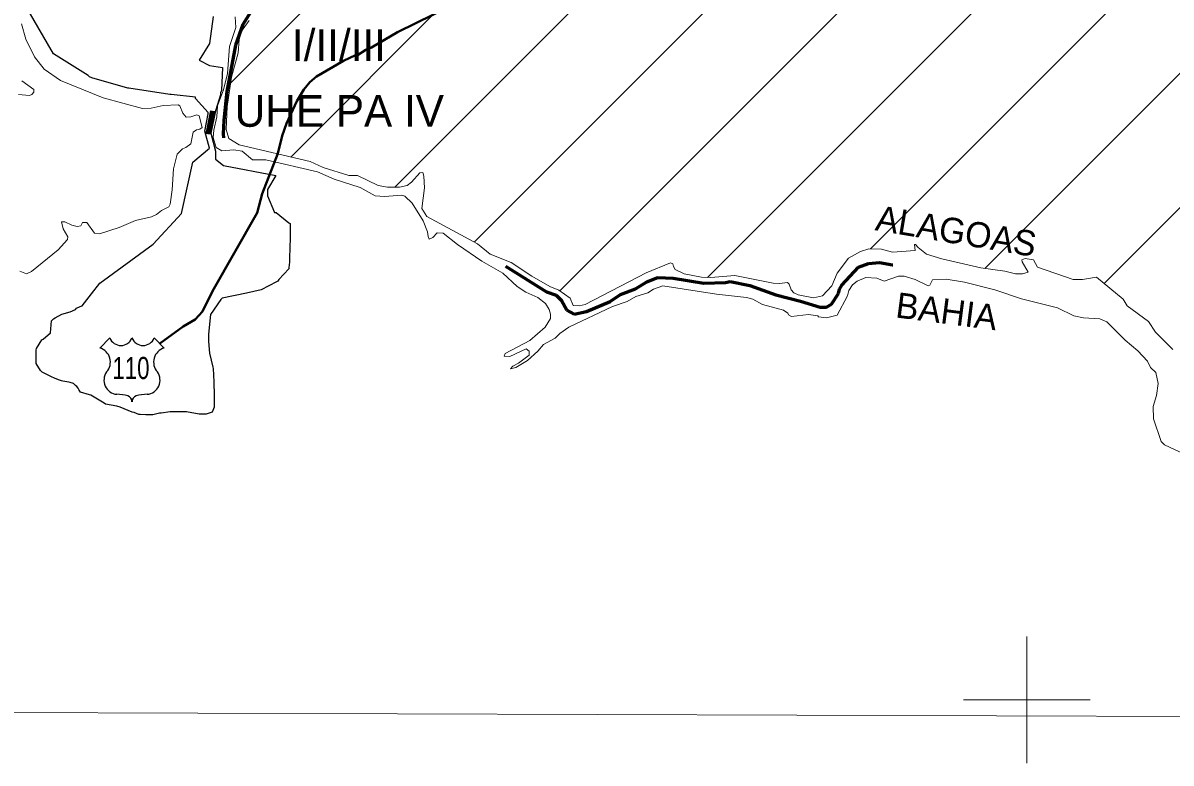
# Model space of a CAD drawing. Extents: x 553962 to 842807, y 8883888 to 9032388.
# Drawn here: x 584142 to 602280, y 8949000 to 8960686 of the extents above; entities that cross this region are included whole.
import ezdxf
from ezdxf.enums import TextEntityAlignment as Align

# ---------------------------------------------------------------- set-up
doc = ezdxf.new("R2010")
doc.units = 0
doc.header["$LTSCALE"] = 160
doc.linetypes.add('LONG_DASH_SHORT_DASH', pattern=[9.9, 6, -1.2, 1.5, -1.2])
for name, color, linetype, lineweight in [('1', 7, 'Continuous', 13), ('11', 7, 'Continuous', 25), ('15', 7, 'Continuous', 25), ('2', 7, 'Continuous', 13), ('21', 7, 'Continuous', 25), ('22', 7, 'Continuous', 35), ('27', 7, 'Continuous', 90), ('28', 7, 'Continuous', 13), ('30', 7, 'Continuous', 13), ('34', 7, 'LONG_DASH_SHORT_DASH', 60)]:
    doc.layers.add(name, color=color, linetype=linetype, lineweight=lineweight)

msp = doc.modelspace()

# ---------------------------------------------------------------- linework, layer by layer
at = {"layer": '1'}
for p, q in [((600000, 8949000), (600000, 8951000)), ((599000, 8950000), (601000, 8950000))]:
    msp.add_line(p, q, dxfattribs=at)
at = {"layer": '11'}
for p, q in [((585355.1, 8955553.3), (585515, 8955713.2)), ((586214.4, 8955713.2), (586374.3, 8955553.3))]:
    msp.add_line(p, q, dxfattribs=at)
for centre, radius, start, end in [((585689.9, 8955780.2), 187.2, 200.95927, 339.04073), ((586039.5, 8955780.2), 187.2, 200.95927, 339.04073), ((585293, 8955331.4), 230.3, 317.5721, 74.36886), ((586436.4, 8955331.4), 230.3, 105.62774, 222.4279), ((585646.5, 8955046.3), 224.7, 144.73733, 264.65778), ((586082.9, 8955046.3), 224.7, 275.34222, 35.26267), ((585624.6, 8954232.8), 589.7, 72.89371, 89.90057), ((585770.3, 8954706.2), 94.4, 357.69345, 72.92955), ((585959.1, 8954706.2), 94.4, 107.07045, 182.30655), ((586104.8, 8954232.8), 589.7, 90.09943, 107.10629)]:
    msp.add_arc(centre, radius, start, end, dxfattribs=at)
at = {"layer": '15', "lineweight": 40}
for points in [[(587134, 8956453.8), (587843.6, 8957685.7), (587923.7, 8957988.5), (588169.9, 8958625.1), (588237, 8958904.7), (588304.1, 8959099.5), (588468, 8959448.9), (588578.9, 8959635.8), (588673.7, 8959750.1), (588777.5, 8959843.1), (589203.6, 8960089.7), (589393.4, 8960175.8), (589428.5, 8960178.5), (589560.1, 8960264.6), (589648.9, 8960297.2), (590059.4, 8960543.5), (591188.1, 8961101.4)], [(586304.3, 8955623.3), (586671.7, 8955893.4), (586864.3, 8956001.7), (586980.3, 8956129.6), (587134, 8956453.8)]]:
    msp.add_lwpolyline(points, dxfattribs=at)
at = {"layer": '2'}
msp.add_line((565315.3, 8949866.8), (791497.7, 8949052.2), dxfattribs=at)
at = {"layer": '21', "lineweight": 13}
for points in [[(587493.3, 8960783.2), (587506.9, 8960616.2), (587403.7, 8960314.5), (587373.8, 8959887.7), (587311.1, 8959628.3), (587213.9, 8959375.4), (587204.9, 8959204), (587155.6, 8958993.5), (587145.5, 8958878.4), (587193.6, 8958719.2), (587281.8, 8958666.6), (587474.7, 8958681.2), (587603.9, 8958663), (587767.8, 8958525.1), (587976.7, 8958527.1), (588793.4, 8958337.9), (589059.2, 8958220.1), (589471.1, 8958087), (589708, 8957957.9), (589856.5, 8957947.6), (590127.1, 8957964.8), (590176.9, 8957951.8), (590291.3, 8957841.5), (590464.7, 8957564.3), (590533, 8957388.3), (590544.4, 8957313.3), (590557.7, 8957273.4), (590617.6, 8957300), (590684.2, 8957372.3), (590781.5, 8957369.6), (591005.6, 8957189.1), (591390.8, 8956926.9), (591724.8, 8956737.2), (591949.4, 8956523.8), (592086.2, 8956435.1), (592274.8, 8956349.3), (592397.3, 8956258.1), (592456.5, 8956160.4), (592477.4, 8956090.3), (592474.5, 8956017), (592393.6, 8955882.5), (592147.6, 8955671.4), (591762.8, 8955464.9)], [(586173.8, 8957626.7), (586254.3, 8957662.7), (586330.8, 8957724.2), (586445.4, 8957783.8), (586466.9, 8957824.2), (586500.9, 8958053.6), (586518, 8958381), (586577.3, 8958614.2), (586660.1, 8958701.3), (586717.8, 8958720.8), (586791.8, 8958780.2), (586832.3, 8958962.8), (586883.3, 8959001), (586938.3, 8959007.4), (586974.5, 8959033.2), (586924.3, 8959221.3), (586887.5, 8959234.6), (586794.3, 8959202.9), (586719.8, 8959198.7), (586666.5, 8959264.6), (586621.9, 8959377), (586592.2, 8959394), (586356.5, 8959383.4), (586169.5, 8959338.8), (586028.5, 8959334.8), (585408.8, 8959506.7), (584733.5, 8959776.4), (584476.5, 8959954.9), (584325.6, 8960152.6), (584187.7, 8960432.6), (584121.2, 8960674.7)], [(587368.2, 8959365.5), (587437, 8959830.7), (587541.6, 8960215), (587558.8, 8960425), (587596.7, 8960558.6), (587717.4, 8960723.2)], [(584126, 8959774.3), (584315, 8959638.2), (584312.8, 8959595.8), (584281, 8959557.7), (584244.7, 8959542.8), (584070.6, 8959557.6)], [(594862.5, 8956673.6), (594585.9, 8956725.5), (594444.6, 8956791.6), (594420.1, 8956840.6), (594411.5, 8956881.7), (594373.8, 8956897.2), (593986.5, 8956741.5), (593024.9, 8956242.6), (592929.9, 8956217.7), (592835, 8956222.8), (592789.7, 8956341.7), (592606.3, 8956465.9), (592465.6, 8956523.5), (592181.6, 8956687.1), (591853.4, 8956904.4), (591520.9, 8957037.4), (591321.1, 8957200.7), (590522.6, 8957630), (590445.4, 8957756.5), (590486.6, 8958082.5), (590475.5, 8958269.4), (590460, 8958322.7), (590411.3, 8958320.8), (590281.4, 8958169.9), (590213.4, 8958120.7), (590089.5, 8958093.2), (589901.7, 8958091.4), (589756.1, 8958120.1), (589428.5, 8958275.3), (589288.6, 8958277.6), (588883.2, 8958402.7), (588677.6, 8958496.7), (587555.9, 8958762.2), (587392.7, 8958862), (587351, 8959003.1), (587368.2, 8959365.5)], [(584094.1, 8956768.4), (584197.5, 8956726), (584274.9, 8956764.4), (584696, 8957104.7), (584847.7, 8957267), (584848.5, 8957309.3), (584778.1, 8957437.9), (584753, 8957543.8), (584806, 8957543.7), (584911.7, 8957490.8), (584997.2, 8957473.7), (585058.5, 8957484.5), (585084, 8957533), (585149.7, 8957533.1), (585272.9, 8957365.6), (585351.4, 8957354.8), (585664, 8957458.9), (585918.1, 8957564.8), (586173.8, 8957626.7)], [(602307.6, 8955528.7), (602034.6, 8955801.4), (601924, 8955971.4), (601588.5, 8956218.1), (601523.3, 8956327.4), (601101.6, 8956673.9), (600881.9, 8956635.9), (600732.9, 8956633.6), (600171.5, 8956830.7), (600105.7, 8956947.1), (599975.9, 8956965.8), (599923.2, 8956948.3), (599930.5, 8956912), (600022.6, 8956753.4), (599933.1, 8956722.5), (599825.2, 8956722.6), (599652.7, 8956767.8), (599276.6, 8956821.3), (598658.4, 8956963), (598417.2, 8957037), (598286.2, 8957141.3), (598243.2, 8957190.3), (598226.2, 8957190.3), (598238.1, 8957092.3), (597879.3, 8957064.6), (597707.1, 8957116.2), (597507.8, 8957122.3), (597374.1, 8957077.1), (597186.1, 8956972.4), (597004.9, 8956736.8), (596919, 8956537.3), (596774.8, 8956375.5), (596632.8, 8956343.6), (596391.2, 8956391.8), (596318.4, 8956424.7), (596280.9, 8956471.9), (596249.4, 8956564), (596220.4, 8956588.7), (596094.6, 8956570.7), (595996.6, 8956575.1), (595390.8, 8956696.7), (595007.1, 8956666.9), (594862.5, 8956673.6)], [(597003.9, 8956073.5), (597167.4, 8956377.6), (597189.2, 8956464.2), (597246.3, 8956548.8), (597323.6, 8956610.2), (597458.5, 8956666.4), (597633.6, 8956656.2), (597747.2, 8956610.1), (597972.1, 8956689.8), (598064.1, 8956689.8), (598239.7, 8956635), (598443.1, 8956534.1), (598468, 8956546.2), (598513.2, 8956629.3), (598729.6, 8956640.7), (599018.9, 8956591.1), (599495.2, 8956473.1), (599918.7, 8956332), (600484.8, 8956190.4), (600746.5, 8956064.1), (600895.5, 8956031), (601154.5, 8956013.6), (601268.1, 8955965.7), (601556.7, 8955677.2), (601755.9, 8955508), (601906.3, 8955346.6), (601953.1, 8955243.3), (602040.9, 8955167.5), (602075.2, 8954992.2), (602048.3, 8954806.2), (601997.4, 8954631), (602004.3, 8954436.4), (602125.1, 8954076), (602178.8, 8954026.5), (602495.4, 8953875)], [(591762.8, 8955464.9), (591742.8, 8955422.7), (591836, 8955420.5), (592092.2, 8955540.4), (592137.1, 8955502.8), (592137.1, 8955438.7), (591972.1, 8955314.2), (591880.4, 8955265.1), (591844.9, 8955225.2), (591926.5, 8955246.3), (592111.5, 8955357.7), (592276, 8955503.1), (592363.4, 8955610), (592552.2, 8955708.7), (592624, 8955780.3), (592767.9, 8955885), (593458.4, 8956208.9), (593688.8, 8956290), (593826.7, 8956367.4), (594014.5, 8956427.2), (594104.1, 8956482.6), (594251.8, 8956534.1), (595099, 8956405.8), (595575.6, 8956353.7), (595673.6, 8956322.5), (595827.2, 8956241.5), (596157.4, 8956151.4), (596224.2, 8956103.8), (596238.8, 8956075.3), (596285.2, 8956053), (596551.6, 8956080.4), (596701.6, 8956061.6), (596708.8, 8956044.6), (596839, 8956031.7), (597003.9, 8956073.5)]]:
    msp.add_lwpolyline(points, dxfattribs=at)
at = {"layer": '22', "lineweight": 90}
msp.add_line((587063.6, 8958931), (587133.9, 8959296.6), dxfattribs=at)
at = {"layer": '27'}
msp.add_spline([(592698.5, 8977198.4), (599903.5, 8973292.7), (608459.2, 8968138.2), (612674.8, 8965332.6), (616842, 8962096.4), (620005, 8958671.2), (621134, 8957974.7), (621473.4, 8956805.3), (621586.2, 8956597.5)], degree=3, dxfattribs=at)
at = {"layer": '28', "lineweight": 25}
for points in [[(585356.8, 8956577), (586200.7, 8957194), (586644.6, 8957678.4), (586826.2, 8958485.8), (587088.5, 8958707.8), (587013.2, 8958975.6), (587068.3, 8959252.8), (587068.3, 8959273), (586866.5, 8959495), (586866.5, 8959515.2), (586483.1, 8959555.5), (586463, 8959555.5), (585817.3, 8959656.5), (585797.1, 8959656.5), (585232.1, 8959817.9), (585191.8, 8959838.1), (585171.6, 8959858.3), (584626.8, 8960201.4), (584223.3, 8960887.7)], [(587149, 8960786.7), (587088.5, 8960362.9), (586927, 8960100.5)], [(586927, 8960100.5), (587086.5, 8960016.1), (587293.7, 8959984.2), (587277.8, 8959617.6), (587261.8, 8959585.7), (587261.8, 8959553.8), (587182.2, 8959298.7), (587110, 8958948.6), (587182.2, 8958662.7), (587182.2, 8958533.5), (587309.6, 8958437.9), (588138.3, 8958278.5)], [(588138.3, 8958278.5), (588007.2, 8958058.1), (588007.2, 8957954.4), (588118.3, 8957695.2), (588140.5, 8957695.2), (588340.4, 8957532.3), (588362.6, 8957517.5), (588362.6, 8957339.8), (588362.6, 8957317.5), (588362.6, 8957295.3), (588355.2, 8956976.9), (588355.2, 8956917.6), (588347.8, 8956858.4), (588340.4, 8956836.2), (588340.4, 8956806.5), (588184.9, 8956636.2), (588170.1, 8956606.6), (588147.9, 8956599.2), (587903.6, 8956473.3), (587674.1, 8956421.4), (587289.1, 8956340), (587266.9, 8956317.8), (587104, 8956080.8), (587074.4, 8955769.7), (587074.4, 8955658.7), (587089.2, 8955473.5), (587141, 8955251.3), (587148.4, 8955229.1)], [(587148.4, 8955229.1), (587155.8, 8955021.8), (587155.8, 8954992.1), (587163.2, 8954829.2), (587163.2, 8954644.1), (587163.2, 8954621.8), (587133.6, 8954540.4), (587037.4, 8954510.8), (586926.3, 8954510.8), (586726.4, 8954547.8), (586526.6, 8954547.8), (586467.3, 8954547.8), (586326.7, 8954525.6), (586297.1, 8954525.6), (586193.4, 8954495.9), (586163.8, 8954495.9), (586112, 8954495.9), (586082.3, 8954495.9), (585993.5, 8954503.3), (585971.3, 8954503.3), (585897.3, 8954533), (585867.7, 8954540.4), (585675.2, 8954621.8), (585623.3, 8954636.7), (585445.7, 8954666.3), (585423.5, 8954681.1), (585216.2, 8954807), (585193.9, 8954814.4), (585053.3, 8954858.8), (585031.1, 8954888.5), (585016.3, 8954918.1), (584994.1, 8954947.7), (584971.8, 8954962.5), (584942.2, 8954992.1), (584890.4, 8955006.9), (584868.2, 8955014.3), (584772, 8955029.2), (584749.7, 8955036.6), (584720.1, 8955044), (584653.5, 8955073.6), (584631.3, 8955081), (584601.7, 8955095.8), (584446.2, 8955169.9), (584416.6, 8955199.5), (584350, 8955310.6), (584350, 8955332.8), (584350, 8955473.5), (584350, 8955525.3), (584357.4, 8955547.6), (584438.8, 8955680.9), (584461, 8955695.7), (584579.5, 8955792), (584594.3, 8955984.5), (584623.9, 8956014.1), (584653.5, 8956028.9), (584757.2, 8956088.2), (584816.4, 8956103), (584868.2, 8956117.8), (584890.4, 8956125.2), (584971.8, 8956162.2), (584986.7, 8956184.5), (585045.9, 8956206.7), (585075.5, 8956221.5), (585223.6, 8956406.6), (585356.8, 8956577)]]:
    msp.add_lwpolyline(points, dxfattribs=at)
at = {"layer": '28'}
for points in [[(587148.4, 8955229.1), (587141, 8955251.3), (587089.2, 8955473.5), (587074.4, 8955658.7), (587074.4, 8955769.7), (587104, 8956080.8), (587266.9, 8956317.8), (587289.1, 8956340), (587674.1, 8956421.4), (587903.6, 8956473.3), (588147.9, 8956599.2), (588170.1, 8956606.6), (588184.9, 8956636.2), (588340.4, 8956806.5), (588340.4, 8956836.2), (588347.8, 8956858.4), (588355.2, 8956917.6), (588355.2, 8956976.9), (588362.6, 8957295.3), (588362.6, 8957317.5), (588362.6, 8957339.8), (588362.6, 8957517.5), (588340.4, 8957532.3), (588140.5, 8957695.2), (588118.3, 8957695.2), (588007.2, 8957954.4), (588007.2, 8958058.1), (588138.3, 8958278.5)], [(585356.8, 8956577), (585223.6, 8956406.6), (585075.5, 8956221.5), (585045.9, 8956206.7), (584986.7, 8956184.5), (584971.8, 8956162.2), (584890.4, 8956125.2), (584868.2, 8956117.8), (584816.4, 8956103), (584757.2, 8956088.2), (584653.5, 8956028.9), (584623.9, 8956014.1), (584594.3, 8955984.5), (584579.5, 8955792), (584461, 8955695.7), (584438.8, 8955680.9), (584357.4, 8955547.6), (584350, 8955525.3), (584350, 8955473.5), (584350, 8955332.8), (584350, 8955310.6), (584416.6, 8955199.5), (584446.2, 8955169.9), (584601.7, 8955095.8), (584631.3, 8955081), (584653.5, 8955073.6), (584720.1, 8955044), (584749.7, 8955036.6), (584772, 8955029.2), (584868.2, 8955014.3), (584890.4, 8955006.9), (584942.2, 8954992.1), (584971.8, 8954962.5), (584994.1, 8954947.7), (585016.3, 8954918.1), (585031.1, 8954888.5), (585053.3, 8954858.8), (585193.9, 8954814.4), (585216.2, 8954807), (585423.5, 8954681.1), (585445.7, 8954666.3), (585623.3, 8954636.7), (585675.2, 8954621.8), (585867.7, 8954540.4), (585897.3, 8954533), (585971.3, 8954503.3), (585993.5, 8954503.3), (586082.3, 8954495.9), (586112, 8954495.9), (586163.8, 8954495.9), (586193.4, 8954495.9), (586297.1, 8954525.6), (586326.7, 8954525.6), (586467.3, 8954547.8), (586526.6, 8954547.8), (586726.4, 8954547.8), (586926.3, 8954510.8), (587037.4, 8954510.8), (587133.6, 8954540.4), (587163.2, 8954621.8), (587163.2, 8954644.1), (587163.2, 8954829.2), (587155.8, 8954992.1), (587155.8, 8955021.8), (587148.4, 8955229.1)]]:
    msp.add_lwpolyline(points, dxfattribs=at)
at = {"layer": '30'}
for p, q in [((587424, 8959742.8), (600588.4, 8972907.1)), ((588371.7, 8958569.1), (601945.6, 8972143)), ((590016.4, 8958092.5), (603275.3, 8971351.3)), ((591272.2, 8957227), (604596, 8970550.7)), ((592621.9, 8956455.3), (605901.8, 8969735.2)), ((594957.1, 8956669.2), (607207.6, 8968919.8)), ((597530.8, 8957121.6), (608512.7, 8968103.5)), ((599342.4, 8956811.9), (609798.3, 8967267.8)), ((601224.7, 8956572.8), (611074.7, 8966422.8))]:
    msp.add_line(p, q, dxfattribs=at)
at = {"layer": '34'}
for points in [[(587733.4, 8960846.2), (587616.5, 8960660), (587498.3, 8960337.4), (587362.2, 8959603), (587314, 8959147.2), (587303.2, 8958935.8), (587310.7, 8958873)], [(591763.5, 8956844.7), (592411.2, 8956442.8), (592564.9, 8956388.5), (592651.2, 8956302.3), (592733.4, 8956151.1), (592848.3, 8956090.3), (593046.8, 8956129.1), (593418.6, 8956289.1), (593583.1, 8956399.4), (593816.8, 8956488.1), (593998.4, 8956596.2), (594173.5, 8956669.6), (594413, 8956654.5), (594897.5, 8956576.7), (595243.6, 8956587.5), (595312.5, 8956604.7), (595624.1, 8956539.8), (596038.9, 8956395.1), (596423.7, 8956293.5), (596735, 8956198.4), (596838.5, 8956200.5), (596916.4, 8956245.8), (597028.8, 8956414.3), (597044.2, 8956483.7), (597078.6, 8956544), (597342.3, 8956831.6), (597500, 8956885.7), (597673.4, 8956903.1), (597880.7, 8956866.4), (597885, 8956866.3)]]:
    msp.add_lwpolyline(points, dxfattribs=at)

# ---------------------------------------------------------------- texts
at = {"layer": '11', "width": 0.75}
msp.add_text('110', height=350, dxfattribs=at).set_placement((585848.6, 8955063.3), align=Align.CENTER)
at = {"layer": '22'}
for s, p in [('I/II/III', (589134.4, 8960086.2)), ('UHE PA IV', (589140.4, 8959047.3))]:
    msp.add_text(s, height=500, dxfattribs=at).set_placement(p, align=Align.CENTER)
at = {"layer": '34'}
for s, rotation, p in [('ALAGOAS', 350.452, (598853, 8957203.3)), ('BAHIA', 352.646, (598710.4, 8955935.6))]:
    msp.add_text(s, height=400, rotation=rotation, dxfattribs=at).set_placement(p, align=Align.CENTER)

doc.saveas('drawing.dxf')
